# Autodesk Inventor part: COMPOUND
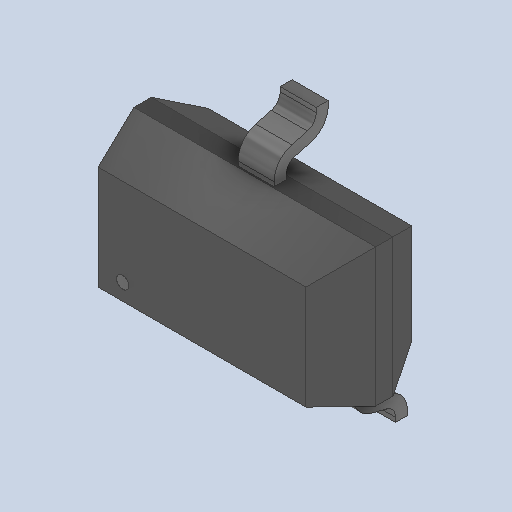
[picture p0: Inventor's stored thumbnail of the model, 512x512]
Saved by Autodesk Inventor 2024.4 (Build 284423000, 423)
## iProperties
Created: 2025-05
Part Number: COMPOUND
Material: Generic
Document SubType Name: Modeling
Designer: AdminForWorker
Density: 1 g/cm^3
Appearance: Default
Title: COMPOUND
Author: AdminForWorker
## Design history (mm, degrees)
feature "Body1"
feature "Body2"
feature "Body3"
feature "Body4"
feature "Body5"
body "Solid1"
body "Solid2"
body "Solid3"
body "Solid4"
body "Solid5"
